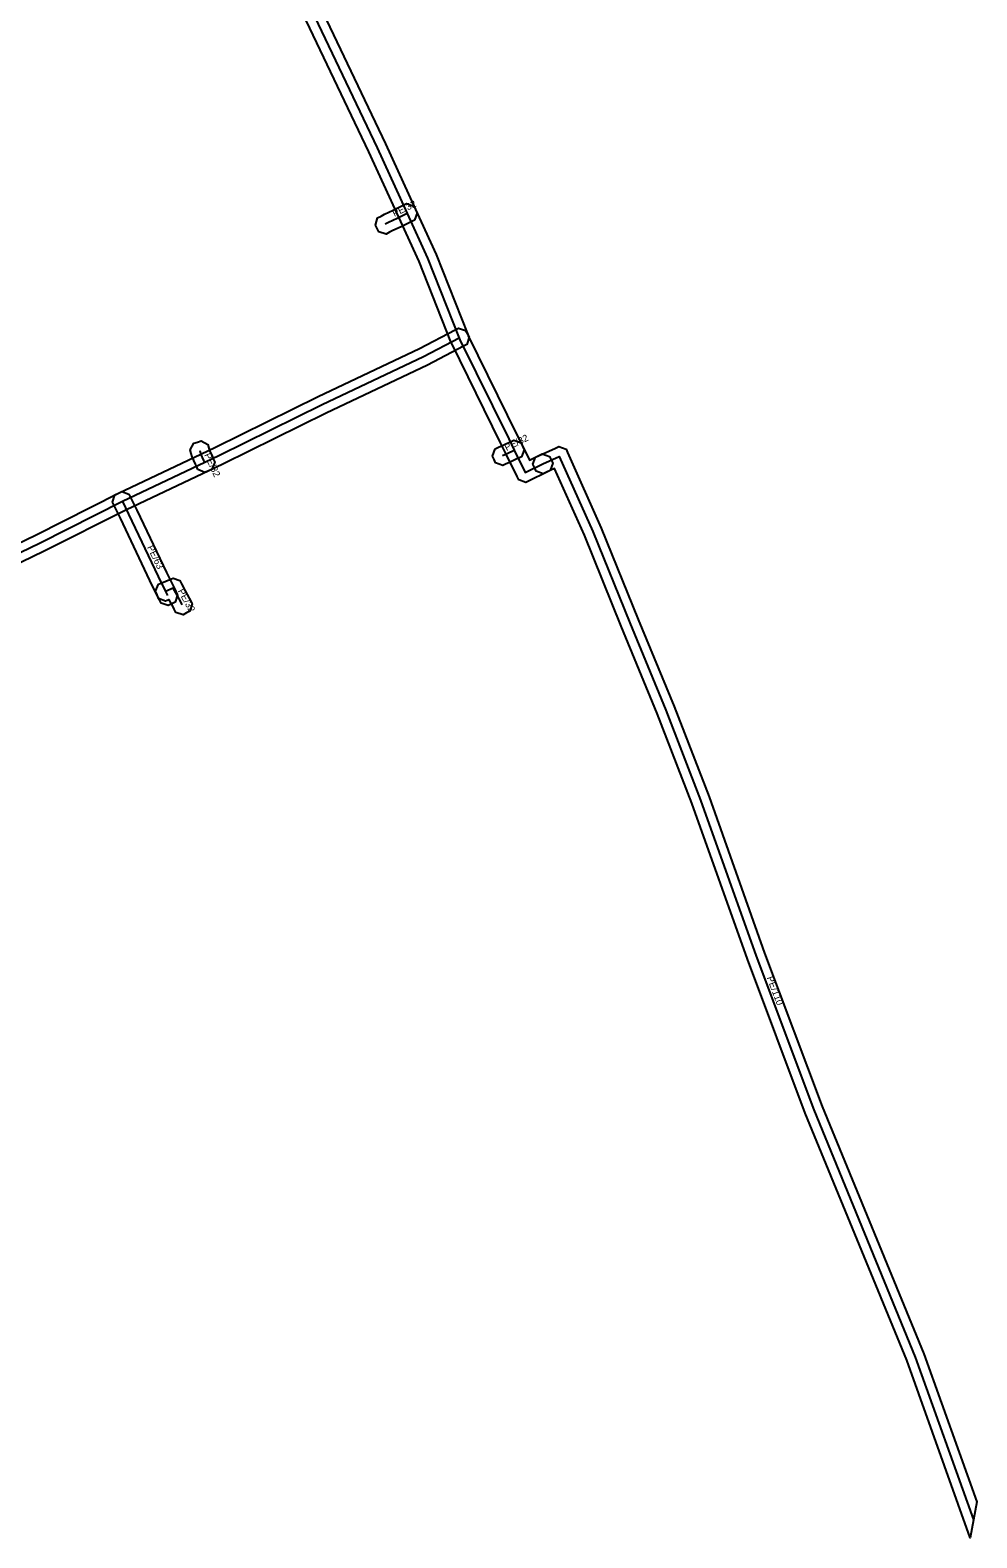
# Model space of a CAD drawing. Extents: x -574390 to -573768, y -1190959 to -1190603.
# Drawn here: x -573870.9 to -573767.7, y -1190958.6 to -1190794.4 of the extents above; entities that cross this region are included whole.
import ezdxf

# ---------------------------------------------------------------- set-up
doc = ezdxf.new("R2010")
doc.units = 0
for name, color, linetype in [('1', 7, 'Continuous'), ('24', 7, 'Continuous'), ('30', 7, 'Continuous')]:
    doc.layers.add(name, color=color, linetype=linetype)

msp = doc.modelspace()

# ---------------------------------------------------------------- linework, layer by layer
at = {"layer": '1'}
for points in [[(-573839.397, -1190791.7), (-573832.194, -1190806.776), (-573828.916, -1190813.929), (-573826.68, -1190818.807), (-573823.228, -1190827.533), (-573823.164, -1190827.676), (-573817.863, -1190838.448), (-573817.262, -1190839.67), (-573816.503, -1190841.213), (-573815.48, -1190840.712), (-573815.108, -1190840.53), (-573814.324, -1190840.798), (-573814.142, -1190841.17), (-573813.96, -1190841.542), (-573814.228, -1190842.326), (-573814.6, -1190842.508), (-573816.52, -1190843.448), (-573816.892, -1190843.63), (-573817.675, -1190843.362), (-573817.857, -1190842.991), (-573819.056, -1190840.552), (-573819.657, -1190839.332), (-573824.976, -1190828.524), (-573825.072, -1190828.307), (-573828.52, -1190819.593), (-573830.734, -1190814.763), (-573834.006, -1190807.624), (-573841.203, -1190792.56)], [(-573886.391, -1190857.132), (-573870.263, -1190849.343), (-573861.299, -1190844.822), (-573852.309, -1190840.56), (-573850.726, -1190839.81), (-573839.535, -1190834.28), (-573828.496, -1190829.064), (-573824.613, -1190827.034), (-573824.246, -1190826.842), (-573823.456, -1190827.09), (-573823.264, -1190827.457), (-573823.072, -1190827.824), (-573823.32, -1190828.614), (-573823.687, -1190828.806), (-573827.604, -1190830.856), (-573838.665, -1190836.08), (-573849.854, -1190841.61), (-573851.453, -1190842.368), (-573860.421, -1190846.618), (-573869.377, -1190851.137), (-573885.509, -1190858.928)]]:
    msp.add_lwpolyline(points, dxfattribs=at)
for points in [[(-573829.017, -1190815.066), (-573829.39, -1190815.246), (-573830.497, -1190815.781), (-573831.401, -1190816.214), (-573831.743, -1190816.394), (-573832.11, -1190816.587), (-573832.901, -1190816.343), (-573833.094, -1190815.977), (-573833.287, -1190815.61), (-573833.043, -1190814.819), (-573832.677, -1190814.626), (-573832.299, -1190814.426), (-573831.363, -1190813.979), (-573830.26, -1190813.446), (-573829.887, -1190813.266), (-573829.105, -1190813.538), (-573828.925, -1190813.911), (-573828.745, -1190814.284)], [(-573852.632, -1190842.243), (-573852.798, -1190841.864), (-573852.884, -1190841.666), (-573853.25, -1190840.858), (-573853.36, -1190840.479), (-573853.476, -1190840.081), (-573853.077, -1190839.355), (-573852.679, -1190839.24), (-573852.281, -1190839.124), (-573851.555, -1190839.523), (-573851.44, -1190839.921), (-573851.37, -1190840.162), (-573851.056, -1190840.854), (-573850.964, -1190841.064), (-573850.799, -1190841.444), (-573851.102, -1190842.215), (-573851.481, -1190842.381), (-573851.861, -1190842.546)], [(-573820.245, -1190839.986), (-573819.869, -1190839.812), (-573819.615, -1190839.695), (-573818.733, -1190839.274), (-573818.575, -1190839.201), (-573818.198, -1190839.029), (-573817.421, -1190839.318), (-573817.249, -1190839.695), (-573817.077, -1190840.072), (-573817.366, -1190840.849), (-573817.743, -1190841.021), (-573817.887, -1190841.086), (-573818.765, -1190841.505), (-573819.031, -1190841.628), (-573819.407, -1190841.802), (-573820.184, -1190841.515), (-573820.358, -1190841.139), (-573820.532, -1190840.763)], [(-573767.747, -1190954.668), (-573768.463, -1190958.597), (-573775.394, -1190939.259), (-573786.451, -1190912.356), (-573792.749, -1190895.583), (-573798.788, -1190878.588), (-573802.579, -1190868.801), (-573806.496, -1190859.308), (-573810.513, -1190849.387), (-573813.754, -1190842.125), (-573814.628, -1190842.521), (-573815.005, -1190842.692), (-573815.78, -1190842.399), (-573815.951, -1190842.022), (-573816.122, -1190841.645), (-573815.829, -1190840.87), (-573815.452, -1190840.699), (-573813.662, -1190839.889), (-573813.284, -1190839.718), (-573812.895, -1190839.865), (-573812.506, -1190840.013), (-573812.337, -1190840.392), (-573808.673, -1190848.603), (-573804.644, -1190858.552), (-573800.721, -1190868.059), (-573796.912, -1190877.892), (-573790.871, -1190894.897), (-573784.589, -1190911.624), (-573773.526, -1190938.541)], [(-573860.144, -1190844.909), (-573859.962, -1190845.281), (-573859.279, -1190846.676), (-573856.06, -1190853.444), (-573855.264, -1190855.06), (-573855.033, -1190855.527), (-573854.85, -1190855.899), (-573855.116, -1190856.684), (-573855.487, -1190856.867), (-573855.859, -1190857.05), (-573856.644, -1190856.784), (-573856.827, -1190856.413), (-573857.058, -1190855.944), (-573857.86, -1190854.316), (-573861.081, -1190847.544), (-573861.758, -1190846.159), (-573861.94, -1190845.787), (-573861.671, -1190845.004), (-573861.299, -1190844.822), (-573860.927, -1190844.64)], [(-573855.343, -1190857.189), (-573855.761, -1190856.419), (-573855.779, -1190856.426), (-573856.162, -1190856.584), (-573856.927, -1190856.267), (-573857.085, -1190855.884), (-573857.243, -1190855.501), (-573856.926, -1190854.736), (-573856.543, -1190854.578), (-573855.692, -1190854.226), (-573855.337, -1190854.079), (-573854.612, -1190854.337), (-573854.43, -1190854.675), (-573854.021, -1190855.434), (-573853.577, -1190856.251), (-573853.443, -1190856.509), (-573853.252, -1190856.876), (-573853.501, -1190857.666), (-573853.869, -1190857.857), (-573854.236, -1190858.048), (-573855.026, -1190857.799), (-573855.217, -1190857.431)]]:
    msp.add_lwpolyline(points, close=True, dxfattribs=at)
at = {"layer": '24'}
for points in [[(-573868.855, -1190732.625), (-573868.8, -1190732.74), (-573868.74, -1190732.863), (-573862.92, -1190744.71), (-573862.16, -1190746.22), (-573854.03, -1190763.49), (-573853.625, -1190764.327), (-573847.67, -1190776.62), (-573840.3, -1190792.13), (-573833.1, -1190807.2), (-573829.825, -1190814.346), (-573827.6, -1190819.2), (-573824.15, -1190827.92), (-573824.07, -1190828.1), (-573818.76, -1190838.89), (-573818.159, -1190840.111), (-573816.96, -1190842.55), (-573815.04, -1190841.61)], [(-573829.825, -1190814.346), (-573830.93, -1190814.88), (-573831.85, -1190815.32), (-573832.21, -1190815.51)], [(-573824.15, -1190827.92), (-573828.05, -1190829.96), (-573839.1, -1190835.18), (-573850.29, -1190840.71), (-573851.881, -1190841.464), (-573860.86, -1190845.72), (-573869.82, -1190850.24), (-573885.95, -1190858.03), (-573896.44, -1190863.26), (-573907.17, -1190868.49), (-573913.645, -1190871.671), (-573918.29, -1190873.95), (-573931.82, -1190880.6), (-573931.23, -1190881.87), (-573927.22, -1190889.97), (-573926.87, -1190890.64), (-573926.79, -1190890.79)], [(-573851.881, -1190841.464), (-573851.97, -1190841.26), (-573852.31, -1190840.51), (-573852.4, -1190840.2)], [(-573819.45, -1190840.72), (-573819.19, -1190840.6), (-573818.31, -1190840.18), (-573818.159, -1190840.111)], [(-573815.04, -1190841.61), (-573813.25, -1190840.8), (-573809.593, -1190848.995), (-573805.57, -1190858.93), (-573801.65, -1190868.43), (-573797.85, -1190878.24), (-573791.81, -1190895.24), (-573785.52, -1190911.99), (-573774.46, -1190938.9), (-573768.105024, -1190956.632663)], [(-573860.86, -1190845.72), (-573860.18, -1190847.11), (-573856.96, -1190853.88), (-573856.161, -1190855.502), (-573855.93, -1190855.97)], [(-573854.33, -1190856.97), (-573854.46, -1190856.72), (-573854.9, -1190855.91), (-573855.31, -1190855.15), (-573856.161, -1190855.502)]]:
    msp.add_lwpolyline(points, dxfattribs=at)

# ---------------------------------------------------------------- texts
at = {"layer": '30'}
for s, rotation, p in [('PE/32', 25.55996517, (-573831.220033, -1190814.723059)), ('PE/32', 25.51387043, (-573819.004302, -1190840.215917)), ('PE/32', 294.3863711, (-573851.960692, -1190840.639356)), ('PE/63', 295.43705807, (-573858.180452, -1190850.693521)), ('PE/32', 298.34569362, (-573854.837901, -1190855.454378)), ('PE/110', 290.58228127, (-573790.655955, -1190897.580582))]:
    msp.add_text(s, height=0.75, rotation=rotation, dxfattribs=at).set_placement(p)

doc.saveas('drawing.dxf')
